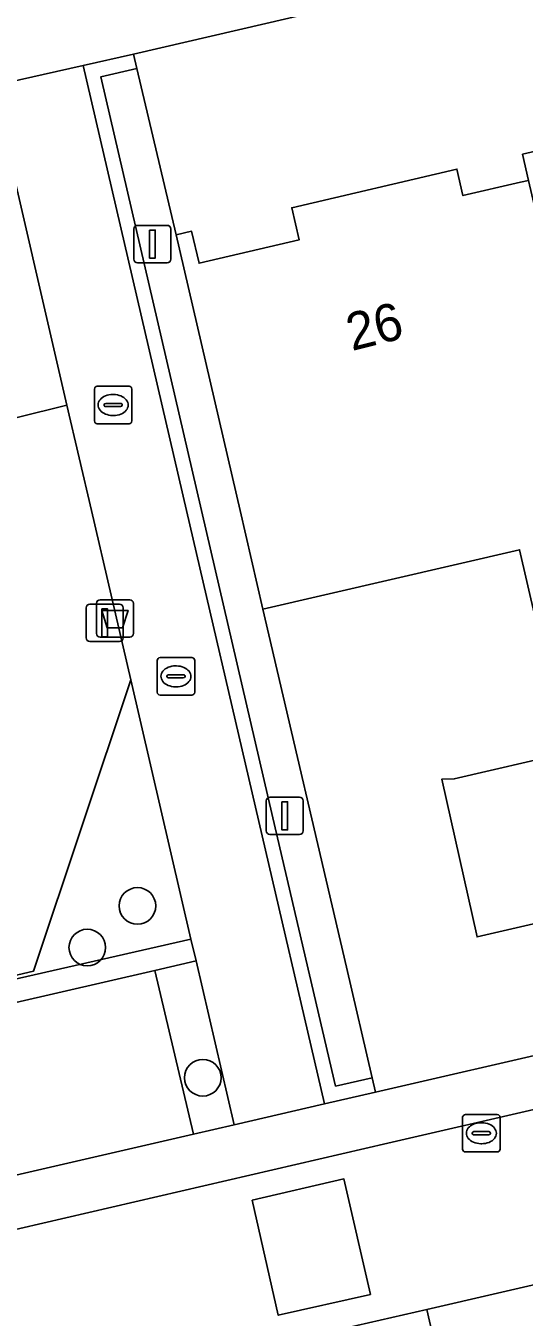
# Model space of a CAD drawing. Extents: x 156412 to 157779, y 382335 to 383768.
# Drawn here: x 156869.59 to 156882.92, y 382728.44 to 382762.95 of the extents above; entities that cross this region are included whole.
import ezdxf

# ---------------------------------------------------------------- set-up
doc = ezdxf.new("R2010")
doc.units = 0
for name, color, linetype in [('IMGEO_Afvalbak', 7, 'Continuous'), ('IMGEO_Boom', 7, 'Continuous'), ('IMGEO_Erf', 7, 'Continuous'), ('IMGEO_Groenvoorziening', 7, 'Continuous'), ('IMGEO_Haag', 7, 'Continuous'), ('IMGEO_Kolk', 7, 'Continuous'), ('IMGEO_Lichtmast', 7, 'Continuous'), ('IMGEO_Muur', 7, 'Continuous'), ('IMGEO_Pand', 7, 'Continuous'), ('IMGEO_Pand_nummerreeks', 7, 'Continuous'), ('IMGEO_Parkeervlak_open', 7, 'Continuous'), ('IMGEO_Rijbaan_lokaal_open', 7, 'Continuous'), ('IMGEO_Terreindeel_zand', 7, 'Continuous'), ('IMGEO_Verkeersbordpaal', 7, 'Continuous'), ('IMGEO_Voetpad_open', 7, 'Continuous')]:
    doc.layers.add(name, color=color, linetype=linetype)

msp = doc.modelspace()

# ---------------------------------------------------------------- linework, layer by layer
at = {"layer": 'IMGEO_Afvalbak'}
for p, q in [((156871.578, 382747.615), (156872.368, 382747.615)), ((156872.368, 382747.615), (156871.578, 382747.615)), ((156871.478, 382746.715), (156871.478, 382747.515)), ((156871.478, 382747.515), (156871.478, 382746.715)), ((156872.468, 382747.515), (156872.468, 382746.715)), ((156872.468, 382746.715), (156872.468, 382747.515)), ((156872.368, 382746.615), (156871.578, 382746.615)), ((156871.578, 382746.615), (156872.368, 382746.615))]:
    msp.add_line(p, q, dxfattribs=at)
msp.add_lwpolyline([(156871.621, 382747.329), (156872.325, 382747.329), (156872.176, 382746.859), (156871.77, 382746.859), (156871.621, 382747.329)], dxfattribs=at)
for centre, start, end in [((156871.578, 382747.515), 90, 180), ((156871.578, 382747.515), 90, 180), ((156872.368, 382747.515), 0, 90), ((156872.368, 382747.515), 360, 90), ((156871.578, 382746.715), 180, 270), ((156871.578, 382746.715), 180, 270), ((156872.368, 382746.715), 270, 0), ((156872.368, 382746.715), 270, 0)]:
    msp.add_arc(centre, 0.1, start, end, dxfattribs=at)
at = {"layer": 'IMGEO_Boom'}
for centre in [(156872.576, 382739.431), (156871.234, 382738.318), (156874.324, 382734.837)]:
    msp.add_circle(centre, 0.489, dxfattribs=at)
at = {"layer": 'IMGEO_Erf'}
for points in [[(156943.044, 382778.552), (156872.472, 382762.194), (156872.562, 382761.81), (156873.608, 382757.366), (156874.024, 382757.463), (156874.225, 382756.608), (156876.903, 382757.235), (156876.702, 382758.09), (156881.117, 382759.124), (156881.279, 382758.417), (156882.815, 382758.771), (156883.036, 382758.822), (156882.873, 382759.523), (156886.673, 382760.407)], [(156887.422, 382739.933), (156881.659, 382738.602), (156880.717, 382742.82), (156881.047, 382742.825), (156884.05, 382743.518), (156882.796, 382748.951), (156875.933, 382747.366), (156878.165, 382737.795), (156878.856, 382734.833), (156878.945, 382734.453), (156946.378, 382750)], [(156950.809, 382744.932), (156880.313, 382728.641), (156881.792, 382722.174), (156884.862, 382722.887)]]:
    msp.add_lwpolyline(points, dxfattribs=at)
at = {"layer": 'IMGEO_Groenvoorziening'}
msp.add_lwpolyline([(156878.165, 382737.795), (156875.933, 382747.366), (156875.32, 382750), (156873.608, 382757.366), (156872.562, 382761.81), (156871.601, 382761.593), (156874.291, 382750), (156876.198, 382741.781), (156877.872, 382734.615), (156878.856, 382734.833)], close=True, dxfattribs=at)
for points in [[(156859.013, 382749.917), (156870.692, 382752.815), (156868.844, 382760.771)], [(156844.907, 382738.164), (156845.816, 382738.144), (156846.714, 382738.005), (156847.586, 382737.749), (156848.417, 382737.38), (156848.772, 382737.18), (156853.317, 382735.569), (156854.742, 382736.058), (156854.968, 382736.079), (156855.174, 382735.984), (156855.325, 382735.725), (156855.67, 382734.37), (156874.007, 382738.543), (156872.397, 382745.475), (156869.8, 382737.69), (156867.314, 382737.103), (156864.097, 382739.12), (156864.987, 382742.012)], [(156807.895, 382722.68), (156810.39, 382723.256), (156811.357, 382723.479), (156816.603, 382724.689), (156817.631, 382724.926), (156822.477, 382726.044), (156824.257, 382726.454), (156829.139, 382727.58), (156830.166, 382727.817), (156835.281, 382728.996), (156836.467, 382729.27), (156852.619, 382732.995), (156861.974, 382735.153), (156866.967, 382736.304), (156867.964, 382736.534), (156873.043, 382737.705), (156874.143, 382737.959), (156874.007, 382738.543), (156855.67, 382734.37), (156851.757, 382733.48), (156838.419, 382730.444), (156834.402, 382729.53), (156803.492, 382722.496)]]:
    msp.add_lwpolyline(points, dxfattribs=at)
at = {"layer": 'IMGEO_Haag'}
msp.add_lwpolyline([(156807.895, 382722.68), (156810.39, 382723.256), (156811.357, 382723.479), (156816.603, 382724.689), (156817.631, 382724.926), (156822.477, 382726.044), (156824.257, 382726.454), (156829.139, 382727.58), (156830.166, 382727.817), (156835.281, 382728.996), (156836.467, 382729.27), (156852.619, 382732.995), (156861.974, 382735.153), (156866.967, 382736.304), (156867.964, 382736.534), (156873.043, 382737.705), (156874.143, 382737.959), (156874.007, 382738.543), (156855.67, 382734.37), (156851.757, 382733.48), (156838.419, 382730.444), (156834.402, 382729.53), (156803.492, 382722.496)], dxfattribs=at)
at = {"layer": 'IMGEO_Kolk'}
for p, q in [((156871.425, 382752.393), (156871.425, 382753.245)), ((156871.5, 382753.319), (156872.352, 382753.319)), ((156872.426, 382753.245), (156872.426, 382752.393)), ((156871.684, 382752.813), (156871.684, 382752.825)), ((156872.122, 382752.776), (156871.724, 382752.776)), ((156871.727, 382752.862), (156872.125, 382752.862)), ((156871.913, 382753.099), (156871.938, 382753.099)), ((156872.168, 382752.825), (156872.168, 382752.813)), ((156871.936, 382752.539), (156871.911, 382752.539)), ((156872.352, 382752.319), (156871.5, 382752.319)), ((156873.105, 382745.14), (156873.105, 382745.992)), ((156873.18, 382746.066), (156874.032, 382746.066)), ((156874.106, 382745.992), (156874.106, 382745.14)), ((156873.364, 382745.56), (156873.364, 382745.572)), ((156873.802, 382745.523), (156873.404, 382745.523)), ((156873.407, 382745.609), (156873.805, 382745.609)), ((156873.593, 382745.846), (156873.618, 382745.846)), ((156873.848, 382745.572), (156873.848, 382745.56)), ((156873.616, 382745.286), (156873.591, 382745.286)), ((156874.032, 382745.066), (156873.18, 382745.066)), ((156881.271, 382732.928), (156881.271, 382733.78)), ((156881.346, 382733.854), (156882.198, 382733.854)), ((156882.272, 382733.78), (156882.272, 382732.928)), ((156881.759, 382733.634), (156881.784, 382733.634)), ((156881.53, 382733.348), (156881.53, 382733.36)), ((156881.968, 382733.311), (156881.57, 382733.311)), ((156881.573, 382733.397), (156881.971, 382733.397)), ((156882.014, 382733.36), (156882.014, 382733.348)), ((156882.198, 382732.854), (156881.346, 382732.854)), ((156881.782, 382733.074), (156881.757, 382733.074))]:
    msp.add_line(p, q, dxfattribs=at)
for points in [[(156871.425, 382752.393), (156871.425, 382753.245)], [(156871.5, 382753.319), (156872.352, 382753.319)], [(156872.426, 382753.245), (156872.426, 382752.393)], [(156872.352, 382752.319), (156871.5, 382752.319)], [(156873.105, 382745.14), (156873.105, 382745.992)], [(156873.18, 382746.066), (156874.032, 382746.066)], [(156874.106, 382745.992), (156874.106, 382745.14)], [(156874.032, 382745.066), (156873.18, 382745.066)], [(156881.271, 382732.928), (156881.271, 382733.78)], [(156881.346, 382733.854), (156882.198, 382733.854)], [(156882.272, 382733.78), (156882.272, 382732.928)], [(156882.198, 382732.854), (156881.346, 382732.854)]]:
    msp.add_lwpolyline(points, dxfattribs=at)
for centre, radius, start, end in [((156871.502, 382753.243), 0.0765, 91.552, 178.448), ((156871.502, 382753.243), 0.0765, 91.552, 178.448), ((156872.35, 382753.243), 0.0765, 1.552, 88.448), ((156872.35, 382753.243), 0.0765, 1.552, 88.448), ((156871.724, 382752.822), 0.0403, 85.8775, 175.7526), ((156871.721, 382752.812), 0.0366, 178.938, 274.7102), ((156872.125, 382752.819), 0.043, 264.8664, 352.4533), ((156872.129, 382752.824), 0.0386, 1.7309, 96.639), ((156871.502, 382752.395), 0.0765, 181.552, 268.448), ((156871.502, 382752.395), 0.0765, 181.552, 268.448), ((156872.35, 382752.395), 0.0765, 271.552, 358.448), ((156872.35, 382752.395), 0.0765, 271.552, 358.448), ((156873.182, 382745.99), 0.0765, 91.552, 178.448), ((156873.182, 382745.99), 0.0765, 91.552, 178.448), ((156874.03, 382745.99), 0.0765, 1.552, 88.448), ((156874.03, 382745.99), 0.0765, 1.552, 88.448), ((156873.404, 382745.569), 0.0403, 85.8775, 175.7526), ((156873.401, 382745.559), 0.0366, 178.938, 274.7102), ((156873.805, 382745.566), 0.043, 264.8664, 352.4533), ((156873.809, 382745.571), 0.0386, 1.7309, 96.639), ((156873.182, 382745.142), 0.0765, 181.552, 268.448), ((156873.182, 382745.142), 0.0765, 181.552, 268.448), ((156874.03, 382745.142), 0.0765, 271.552, 358.448), ((156874.03, 382745.142), 0.0765, 271.552, 358.448), ((156881.348, 382733.778), 0.0765, 91.552, 178.448), ((156881.348, 382733.778), 0.0765, 91.552, 178.448), ((156882.196, 382733.778), 0.0765, 1.552, 88.448), ((156882.196, 382733.778), 0.0765, 1.552, 88.448), ((156881.57, 382733.357), 0.0403, 85.8775, 175.7526), ((156881.567, 382733.347), 0.0366, 178.938, 274.7102), ((156881.971, 382733.354), 0.043, 264.8664, 352.4533), ((156881.975, 382733.359), 0.0386, 1.7309, 96.639), ((156881.348, 382732.93), 0.0765, 181.552, 268.448), ((156881.348, 382732.93), 0.0765, 181.552, 268.448), ((156882.196, 382732.93), 0.0765, 271.552, 358.448), ((156882.196, 382732.93), 0.0765, 271.552, 358.448)]:
    msp.add_arc(centre, radius, start, end, dxfattribs=at)
for centre, major_axis, ratio, start_param, end_param in [((156871.912, 382752.819), (-0.387, 0.002), 0.722429, 4.712389, 7.853982), ((156871.937, 382752.819), (-0.39, 0.002), 0.717154, 1.570796, 4.712389), ((156873.592, 382745.566), (-0.387, 0.002), 0.722429, 4.712389, 7.853982), ((156873.617, 382745.566), (-0.39, 0.002), 0.717154, 1.570796, 4.712389), ((156881.758, 382733.354), (-0.387, 0.002), 0.722429, 4.712389, 7.853982), ((156881.783, 382733.354), (-0.39, 0.002), 0.717154, 1.570796, 4.712389)]:
    msp.add_ellipse(centre, major_axis=major_axis, ratio=ratio, start_param=start_param, end_param=end_param, dxfattribs=at)
at = {"layer": 'IMGEO_Lichtmast'}
for p, q in [((156872.58, 382757.621), (156873.37, 382757.621)), ((156873.37, 382757.621), (156872.58, 382757.621)), ((156872.48, 382756.721), (156872.48, 382757.521)), ((156872.48, 382757.521), (156872.48, 382756.721)), ((156873.47, 382757.521), (156873.47, 382756.721)), ((156873.47, 382756.721), (156873.47, 382757.521)), ((156873.37, 382756.621), (156872.58, 382756.621)), ((156872.58, 382756.621), (156873.37, 382756.621)), ((156876.02, 382741.439), (156876.02, 382742.239)), ((156876.02, 382742.239), (156876.02, 382741.439)), ((156876.12, 382742.339), (156876.91, 382742.339)), ((156876.91, 382742.339), (156876.12, 382742.339)), ((156877.01, 382742.239), (156877.01, 382741.439)), ((156877.01, 382741.439), (156877.01, 382742.239)), ((156876.91, 382741.339), (156876.12, 382741.339)), ((156876.12, 382741.339), (156876.91, 382741.339))]:
    msp.add_line(p, q, dxfattribs=at)
for points in [[(156872.9, 382757.496), (156873.05, 382757.496), (156873.05, 382756.746), (156872.9, 382756.746), (156872.9, 382757.496)], [(156876.44, 382742.214), (156876.59, 382742.214), (156876.59, 382741.464), (156876.44, 382741.464), (156876.44, 382742.214)]]:
    msp.add_lwpolyline(points, dxfattribs=at)
for centre, start, end in [((156872.58, 382757.521), 90, 180), ((156872.58, 382757.521), 90, 180), ((156873.37, 382757.521), 0, 90), ((156873.37, 382757.521), 360, 90), ((156872.58, 382756.721), 180, 270), ((156872.58, 382756.721), 180, 270), ((156873.37, 382756.721), 270, 0), ((156873.37, 382756.721), 270, 0), ((156876.12, 382742.239), 90, 180), ((156876.12, 382742.239), 90, 180), ((156876.91, 382742.239), 0, 90), ((156876.91, 382742.239), 360, 90), ((156876.12, 382741.439), 180, 270), ((156876.12, 382741.439), 180, 270), ((156876.91, 382741.439), 270, 0), ((156876.91, 382741.439), 270, 0)]:
    msp.add_arc(centre, 0.1, start, end, dxfattribs=at)
at = {"layer": 'IMGEO_Muur'}
msp.add_lwpolyline([(156874.291, 382750), (156871.601, 382761.593), (156872.562, 382761.81), (156872.472, 382762.194), (156871.125, 382761.892), (156873.89, 382750), (156877.577, 382734.138), (156878.945, 382734.453), (156878.856, 382734.833), (156877.872, 382734.615), (156876.198, 382741.781)], close=True, dxfattribs=at)
msp.add_lwpolyline([(156875.933, 382747.366), (156878.165, 382737.795)], dxfattribs=at)
at = {"layer": 'IMGEO_Pand'}
for points in [[(156890.751, 382750.788), (156888.587, 382760.104), (156888.37, 382760.054), (156886.835, 382759.7), (156886.673, 382760.407), (156882.873, 382759.523), (156883.036, 382758.822), (156885.085, 382750), (156885.2, 382749.506), (156888.456, 382750.258), (156889.717, 382744.826), (156887.292, 382744.266), (156886.461, 382744.074), (156887.422, 382739.933), (156892.974, 382741.215), (156892.013, 382745.355), (156890.934, 382750)], [(156887.422, 382739.933), (156886.461, 382744.074), (156885.2, 382749.506), (156885.085, 382750), (156883.036, 382758.822), (156882.815, 382758.771), (156881.279, 382758.417), (156881.117, 382759.124), (156876.702, 382758.09), (156876.903, 382757.235), (156874.225, 382756.608), (156874.024, 382757.463), (156873.608, 382757.366), (156875.32, 382750), (156875.933, 382747.366), (156882.796, 382748.951), (156884.05, 382743.518), (156881.047, 382742.825), (156880.717, 382742.82), (156881.659, 382738.602)]]:
    msp.add_lwpolyline(points, close=True, dxfattribs=at)
at = {"layer": 'IMGEO_Parkeervlak_open'}
msp.add_lwpolyline([(156873.043, 382737.705), (156867.964, 382736.534), (156868.975, 382732.152), (156874.073, 382733.33)], close=True, dxfattribs=at)
at = {"layer": 'IMGEO_Rijbaan_lokaal_open'}
for points in [[(156954.997, 382755.422), (156950.885, 382751.332), (156949.815, 382749.383), (156929.495, 382744.678), (156907.413, 382739.578), (156879.275, 382733.088), (156868.803, 382730.665), (156830.401, 382721.812), (156805.031, 382715.955), (156791.204, 382712.755), (156730.522, 382698.738), (156728.301, 382699.143), (156722.872, 382699.769)], [(156876.422, 382727.751), (156877.423, 382727.98), (156877.821, 382728.071), (156880.313, 382728.641), (156950.809, 382744.932), (156952.459, 382744.394), (156957.65, 382743.178)]]:
    msp.add_lwpolyline(points, dxfattribs=at)
for points in [[(156875.645, 382731.565), (156878.099, 382732.133), (156878.807, 382729.045), (156876.341, 382728.49)], [(156878.099, 382732.133), (156875.645, 382731.565), (156876.341, 382728.49), (156878.807, 382729.045)]]:
    msp.add_lwpolyline(points, close=True, dxfattribs=at)
at = {"layer": 'IMGEO_Terreindeel_zand'}
for points in [[(156871.346, 382750), (156870.692, 382752.815), (156859.013, 382749.917), (156857.894, 382747.676), (156860.026, 382745.114)], [(156864.987, 382742.012), (156864.097, 382739.12), (156867.314, 382737.103), (156869.8, 382737.69), (156872.397, 382745.475), (156871.346, 382750)]]:
    msp.add_lwpolyline(points, dxfattribs=at)
at = {"layer": 'IMGEO_Verkeersbordpaal'}
for p, q in [((156871.203, 382746.597), (156871.203, 382747.397)), ((156871.203, 382747.397), (156871.203, 382746.597)), ((156871.303, 382747.497), (156872.093, 382747.497)), ((156872.093, 382747.497), (156871.303, 382747.497)), ((156872.193, 382747.397), (156872.193, 382746.597)), ((156872.193, 382746.597), (156872.193, 382747.397)), ((156872.093, 382746.497), (156871.303, 382746.497)), ((156871.303, 382746.497), (156872.093, 382746.497))]:
    msp.add_line(p, q, dxfattribs=at)
msp.add_lwpolyline([(156871.623, 382747.372), (156871.773, 382747.372), (156871.773, 382746.622), (156871.623, 382746.622), (156871.623, 382747.372)], dxfattribs=at)
for centre, start, end in [((156871.303, 382747.397), 90, 180), ((156871.303, 382747.397), 90, 180), ((156872.093, 382747.397), 0, 90), ((156872.093, 382747.397), 360, 90), ((156871.303, 382746.597), 180, 270), ((156871.303, 382746.597), 180, 270), ((156872.093, 382746.597), 270, 0), ((156872.093, 382746.597), 270, 0)]:
    msp.add_arc(centre, 0.1, start, end, dxfattribs=at)
at = {"layer": 'IMGEO_Voetpad_open'}
for points in [[(156807.635, 382747.256), (156812.585, 382748.399), (156819.521, 382750), (156841.91, 382755.169), (156846.252, 382756.171), (156868.702, 382761.353), (156871.125, 382761.892), (156872.472, 382762.194), (156943.044, 382778.552)], [(156946.378, 382750), (156878.945, 382734.453), (156877.577, 382734.138), (156875.16, 382733.581), (156874.073, 382733.33), (156868.975, 382732.152), (156867.967, 382731.919), (156863.097, 382730.795), (156853.63, 382728.608), (156837.468, 382724.874), (156836.315, 382724.608), (156831.175, 382723.421), (156830.157, 382723.186), (156825.272, 382722.057), (156823.524, 382721.654), (156818.691, 382720.537), (156817.63, 382720.292), (156812.391, 382719.082), (156811.426, 382718.859), (156808.902, 382718.276)], [(156805.031, 382715.955), (156830.401, 382721.812), (156868.803, 382730.665), (156879.275, 382733.088), (156907.413, 382739.578)]]:
    msp.add_lwpolyline(points, dxfattribs=at)
for points in [[(156873.89, 382750), (156871.125, 382761.892), (156868.702, 382761.353), (156868.844, 382760.771), (156870.692, 382752.815), (156871.346, 382750), (156872.397, 382745.475), (156874.007, 382738.543), (156874.143, 382737.959), (156875.16, 382733.581), (156877.577, 382734.138)], [(156874.143, 382737.959), (156873.043, 382737.705), (156874.073, 382733.33), (156875.16, 382733.581)], [(156887.6, 382696.735), (156887.099, 382698.962), (156886.753, 382700.415), (156886.263, 382702.64), (156884.253, 382711.523), (156881.792, 382722.174), (156880.313, 382728.641), (156877.821, 382728.071), (156884.257, 382699.814), (156882.912, 382699.525), (156882.027, 382699.321), (156882.329, 382697.898), (156888.288, 382671.973), (156893.061, 382673.083), (156892.419, 382675.776), (156892.274, 382676.411), (156890.292, 382685.06)]]:
    msp.add_lwpolyline(points, close=True, dxfattribs=at)

# ---------------------------------------------------------------- texts
at = {"layer": 'IMGEO_Pand_nummerreeks'}
msp.add_text('26', height=1, rotation=14.089, dxfattribs=at).set_placement((156878.308, 382754.258))

doc.saveas('drawing.dxf')
